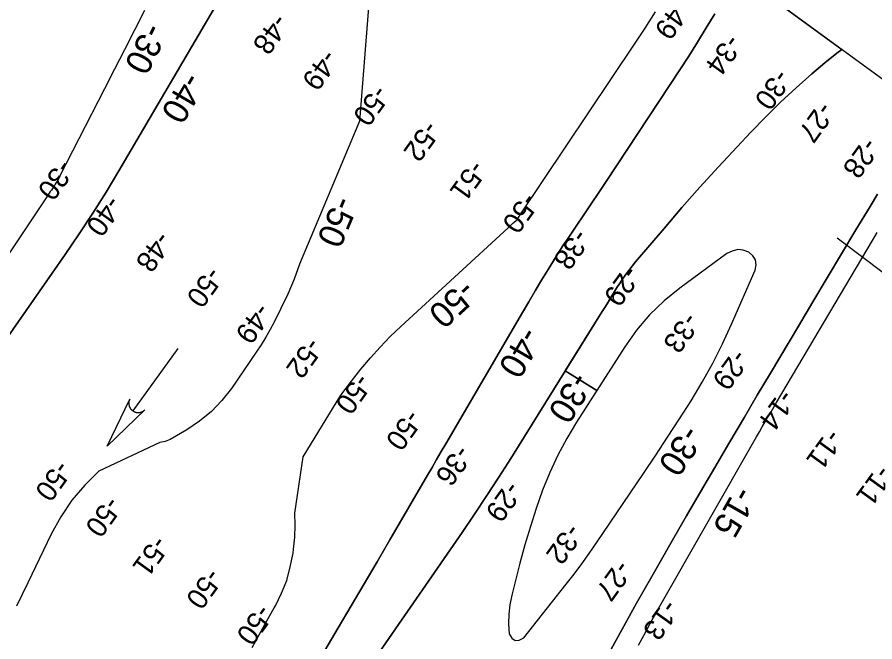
# Model space of a CAD drawing. Extents: x 3879599 to 3900814, y 146526 to 168888.
# Drawn here: x 3895080 to 3896475, y 160981 to 161997 of the extents above; entities that cross this region are included whole.
import ezdxf

# ---------------------------------------------------------------- set-up
doc = ezdxf.new("R2010")
doc.units = 0
for name, color, linetype in [('V-GRID-FRAM', 7, 'Continuous'), ('V-LEVE-TOET', 7, 'Continuous'), ('V-RIVR-RANG', 7, 'Continuous'), ('V-STRM-FLOW', 7, 'Continuous'), ('V-TOPO-DPTH', 7, 'Continuous'), ('V-TOPO-MAJR', 7, 'Continuous'), ('V-TOPO-MAJR-IDEN', 7, 'Continuous'), ('V-TOPO-MINR', 7, 'Continuous'), ('V-TOPO-MINR-IDEN', 7, 'Continuous')]:
    doc.layers.add(name, color=color, linetype=linetype)

msp = doc.modelspace()

# ---------------------------------------------------------------- linework, layer by layer
at = {"layer": 'V-GRID-FRAM'}
msp.add_lwpolyline([(3898776.6, 160226.4), (3889730.7, 148455.2), (3882888.9, 153284.4), (3891901.5, 165241.3), (3898776.6, 160226.4)], dxfattribs=at)
at = {"layer": 'V-LEVE-TOET'}
msp.add_lwpolyline([(3897419.3, 160907.4), (3897311, 160985.3), (3897169.2, 161092), (3896967.9, 161235.4), (3896798.9, 161357), (3896744.2, 161395.8), (3896682.3, 161439.8), (3896491.3, 161579.2), (3896414.2, 161636.9)], dxfattribs=at)
at = {"layer": 'V-STRM-FLOW'}
msp.add_line((3895341.7, 161457.7), (3895268.2, 161356.4), dxfattribs=at)
msp.add_lwpolyline([(3895287.7, 161357.7), (3895226.6, 161299), (3895263.4, 161375.3), (3895262.8, 161373.9), (3895262.4, 161372.5), (3895262.2, 161371.9), (3895262.1, 161371.4), (3895262, 161370.8), (3895262, 161370.2), (3895261.9, 161369.6), (3895261.9, 161368.9), (3895261.9, 161368.1), (3895261.9, 161367.7), (3895262, 161367.1), (3895262.1, 161366.4), (3895262.2, 161365.9), (3895262.3, 161365.2), (3895262.4, 161364.9), (3895262.5, 161364.4), (3895262.7, 161363.9), (3895262.8, 161363.4), (3895263, 161363), (3895263.2, 161362.6), (3895263.4, 161362), (3895263.7, 161361.5), (3895263.9, 161361.1), (3895264.2, 161360.6), (3895264.5, 161360.2), (3895264.7, 161359.9), (3895264.9, 161359.6), (3895265.2, 161359.2), (3895265.5, 161358.8), (3895265.9, 161358.4), (3895266.2, 161358.1), (3895266.5, 161357.8), (3895266.9, 161357.4), (3895267.2, 161357.1), (3895267.7, 161356.8), (3895268.2, 161356.4), (3895268.4, 161356.2), (3895268.6, 161356.1), (3895268.9, 161355.9), (3895269.2, 161355.7), (3895269.5, 161355.5), (3895269.8, 161355.3), (3895270.2, 161355.2), (3895270.4, 161355), (3895270.8, 161354.9), (3895271.1, 161354.7), (3895271.4, 161354.6), (3895272, 161354.4), (3895272.3, 161354.2), (3895272.6, 161354.2), (3895273, 161354), (3895273.3, 161354), (3895273.7, 161353.9), (3895274.1, 161353.8), (3895274.5, 161353.7), (3895274.8, 161353.6), (3895275.1, 161353.6), (3895275.5, 161353.6), (3895275.8, 161353.5), (3895276.2, 161353.5), (3895276.6, 161353.5), (3895277.1, 161353.5), (3895277.6, 161353.5), (3895277.9, 161353.5), (3895278.3, 161353.5), (3895278.7, 161353.6), (3895279.1, 161353.6), (3895279.4, 161353.6), (3895279.9, 161353.7), (3895280, 161353.7), (3895280.3, 161353.8), (3895280.5, 161353.8), (3895280.8, 161353.9), (3895281.2, 161354), (3895281.6, 161354.1), (3895281.9, 161354.2), (3895282.2, 161354.3), (3895282.6, 161354.5), (3895282.8, 161354.6), (3895283.2, 161354.7), (3895283.6, 161354.9), (3895283.9, 161355), (3895284.1, 161355.1), (3895284.3, 161355.2), (3895284.5, 161355.3), (3895284.8, 161355.5), (3895285, 161355.7), (3895285.3, 161355.8), (3895285.6, 161356), (3895285.9, 161356.3), (3895286.1, 161356.4), (3895286.4, 161356.6), (3895286.8, 161356.9), (3895287.1, 161357.1), (3895287.3, 161357.3), (3895287.4, 161357.5), (3895287.6, 161357.6)], close=True, dxfattribs=at)
at = {"layer": 'V-TOPO-DPTH'}
msp.add_line((3896253.5, 162066.8), (3896422, 161943.9), dxfattribs=at)
for points in [[(3894988.9, 161367.9), (3895158.5, 161610.6), (3895181.2, 161644), (3895203.5, 161677.8), (3895224.9, 161712.1), (3895245.8, 161746.7), (3895404.5, 162016.9), (3895405.5, 162018.7), (3895407.7, 162022.5), (3895409.9, 162026.1), (3895411.5, 162028.7), (3895412.3, 162030.1), (3895587.5, 162333.5), (3895598.3, 162352.6), (3895608.9, 162371.9), (3895619.1, 162391.3), (3895629, 162410.9), (3895669.6, 162492.7)], [(3894988.9, 161367.9), (3895158.5, 161610.6), (3895181.2, 161644), (3895203.5, 161677.8), (3895224.9, 161712.1), (3895245.8, 161746.7), (3895404.5, 162016.9), (3895405.5, 162018.7), (3895407.7, 162022.5), (3895409.9, 162026.1), (3895411.5, 162028.7), (3895412.3, 162030.1), (3895587.5, 162333.5), (3895598.3, 162352.6), (3895608.9, 162371.9), (3895619.1, 162391.3), (3895629, 162410.9), (3895669.6, 162492.7)], [(3895287.3, 162007.6), (3895271.1, 161975.6), (3895254.9, 161943.6), (3895238.6, 161911.7), (3895222.2, 161879.7), (3895149.1, 161737.4), (3895147.8, 161734.9), (3895146.5, 161732.4), (3895145.2, 161730), (3895143.8, 161727.6), (3895142.2, 161724.8), (3895140.9, 161722.7), (3895140.3, 161721.7), (3895137.6, 161717.8), (3895135.9, 161715.3), (3895134.2, 161712.8), (3895132.6, 161710.3), (3895130.9, 161707.8), (3894959.4, 161450.9)], [(3895287.3, 162007.6), (3895271.1, 161975.6), (3895254.9, 161943.6), (3895238.6, 161911.7), (3895222.2, 161879.7), (3895149.1, 161737.4), (3895147.8, 161734.9), (3895146.5, 161732.4), (3895145.2, 161730), (3895143.8, 161727.6), (3895142.2, 161724.8), (3895140.9, 161722.7), (3895140.3, 161721.7), (3895137.6, 161717.8), (3895135.9, 161715.3), (3895134.2, 161712.8), (3895132.6, 161710.3), (3895130.9, 161707.8), (3894959.4, 161450.9)], [(3895569.8, 160948.3), (3895602.5, 161003.3), (3895623.7, 161039), (3895644.8, 161074.8), (3895665.8, 161110.6), (3895686.7, 161146.6), (3895747.6, 161251.5), (3895755.1, 161264.3), (3895762.5, 161277.1), (3895769.9, 161289.9), (3895777.4, 161302.7), (3895902.2, 161516.3), (3895912.5, 161533.8), (3895922.9, 161551.3), (3895933.4, 161568.7), (3895944, 161586), (3895956.9, 161607), (3895961.1, 161613.8), (3895965.4, 161620.5), (3895969.8, 161627.2), (3895974.2, 161633.9), (3895989.8, 161656.8), (3896002, 161674.9), (3896014.1, 161693), (3896026.3, 161711.2), (3896038.3, 161729.4), (3896158, 161910.6), (3896172.7, 161933.2), (3896187.2, 161956), (3896201.3, 161979), (3896215.2, 162002.1)], [(3896215.2, 162002.1), (3896201.3, 161979), (3896187.2, 161956), (3896172.7, 161933.2), (3896158, 161910.6), (3896038.3, 161729.4), (3896026.3, 161711.2), (3896014.1, 161693), (3896002, 161674.9), (3895989.8, 161656.8), (3895974.2, 161633.9), (3895969.8, 161627.2), (3895965.4, 161620.5), (3895961.1, 161613.8), (3895956.9, 161607), (3895944, 161586), (3895933.4, 161568.7), (3895922.9, 161551.3), (3895912.5, 161533.8), (3895902.2, 161516.3), (3895777.4, 161302.7), (3895769.9, 161289.9), (3895762.5, 161277.1), (3895755.1, 161264.3), (3895747.6, 161251.5), (3895686.7, 161146.6), (3895665.8, 161110.6), (3895644.8, 161074.8), (3895623.7, 161039), (3895602.5, 161003.3), (3895569.8, 160948.3)], [(3896422, 161943.9), (3896413.7, 161937.8), (3896394.1, 161922.1), (3896373.2, 161904.3), (3896347.4, 161881.5), (3896322.1, 161858.2), (3896297.6, 161834.1), (3896273.6, 161809.4), (3896251.3, 161785.8), (3896220.9, 161753.2), (3896191, 161720.2), (3896161.5, 161686.8), (3896132.5, 161653), (3896086.2, 161598.5), (3896080.7, 161591.7), (3896075.3, 161584.7), (3896070.1, 161577.6), (3896065.1, 161570.4), (3896058.8, 161561.1), (3896057, 161558.4), (3896055.3, 161555.8), (3896053.6, 161553.1), (3896052, 161550.4), (3896047.6, 161543.1), (3896043.8, 161536.7), (3896039.9, 161530.4), (3896036, 161524.1), (3896032.1, 161517.7), (3895883.2, 161279), (3895863.9, 161248.6), (3895844.4, 161218.4), (3895824.4, 161188.4), (3895804.1, 161158.6), (3895660.6, 160950.9)], [(3896023, 161389.3), (3895971.8, 161421.1), (3896032.1, 161517.7), (3896036, 161524.1), (3896039.9, 161530.4), (3896043.8, 161536.7), (3896047.6, 161543.1), (3896052, 161550.4), (3896053.6, 161553.1), (3896055.3, 161555.8), (3896057, 161558.4), (3896058.8, 161561.1), (3896065.1, 161570.4), (3896070.1, 161577.6), (3896075.3, 161584.7), (3896080.7, 161591.7), (3896086.2, 161598.5), (3896132.5, 161653), (3896161.5, 161686.8), (3896191, 161720.2), (3896220.9, 161753.2), (3896251.3, 161785.8), (3896273.6, 161809.4), (3896297.6, 161834.1), (3896322.1, 161858.2), (3896347.4, 161881.5), (3896373.2, 161904.3), (3896394.1, 161922.1), (3896413.7, 161937.8), (3896422, 161943.9)], [(3896479.8, 161708.8), (3896467.6, 161688.7), (3896444.8, 161650.8), (3896421.3, 161611.7), (3896397.9, 161572.5), (3896374.5, 161533.4), (3896351.2, 161494.2), (3896305.6, 161417.4), (3896294.9, 161399.6), (3896284.3, 161381.7), (3896273.8, 161363.8), (3896263.2, 161345.9), (3896238, 161303.3), (3896215, 161264.1), (3896192, 161224.8), (3896169.2, 161185.4), (3896146.5, 161145.9), (3896112.5, 161086.6), (3896100.2, 161065), (3896088, 161043.4), (3896075.9, 161021.8), (3896063.9, 161000.1), (3895995.7, 160875.9)], [(3896479.8, 161708.8), (3896467.6, 161688.7), (3896444.8, 161650.8), (3896421.3, 161611.7), (3896397.9, 161572.5), (3896374.5, 161533.4), (3896351.2, 161494.2), (3896305.6, 161417.4), (3896294.9, 161399.6), (3896284.3, 161381.7), (3896273.8, 161363.8), (3896263.2, 161345.9), (3896238, 161303.3), (3896215, 161264.1), (3896192, 161224.8), (3896169.2, 161185.4), (3896146.5, 161145.9), (3896112.5, 161086.6), (3896100.2, 161065), (3896088, 161043.4), (3896075.9, 161021.8), (3896063.9, 161000.1), (3895995.7, 160875.9)], [(3895890.5, 160982.5), (3895897, 160983.2), (3895904.5, 160987.1), (3895973.6, 161074.2), (3895986.3, 161090.7), (3895998.8, 161107.4), (3896011, 161124.3), (3896022.9, 161141.4), (3896099.4, 161254.6), (3896119, 161283.9), (3896138.4, 161313.4), (3896157.6, 161343), (3896176.5, 161372.8), (3896194.6, 161403), (3896211.8, 161433.8), (3896227.5, 161465.2), (3896242.4, 161497.2), (3896280.7, 161584.9), (3896282.2, 161593.7), (3896281.4, 161601.6), (3896277.1, 161608.4), (3896270.6, 161614.4), (3896261.4, 161617.4), (3896252.4, 161618.4), (3896243.6, 161616.2), (3896234.9, 161612), (3896158, 161555.8), (3896132.5, 161534.9), (3896108.8, 161512.3), (3896087.7, 161487.2), (3896068.5, 161460.4), (3895990.1, 161337.8), (3895974.2, 161311.2), (3895959.6, 161283.9), (3895946.7, 161255.8), (3895935, 161227.1), (3895924.7, 161197.7), (3895915.1, 161168.2), (3895906.3, 161138.4), (3895898.1, 161108.4), (3895884.9, 161056.6), (3895881.9, 161041), (3895880, 161025.4), (3895879.8, 161009.6), (3895880.8, 160993.8), (3895885.2, 160986.6), (3895890.5, 160982.5)], [(3895890.5, 160982.5), (3895897, 160983.2), (3895904.5, 160987.1), (3895973.6, 161074.2), (3895986.3, 161090.7), (3895998.8, 161107.4), (3896011, 161124.3), (3896022.9, 161141.4), (3896099.4, 161254.6), (3896119, 161283.9), (3896138.4, 161313.4), (3896157.6, 161343), (3896176.5, 161372.8), (3896194.6, 161403), (3896211.8, 161433.8), (3896227.5, 161465.2), (3896242.4, 161497.2), (3896280.7, 161584.9), (3896282.2, 161593.7), (3896281.4, 161601.6), (3896277.1, 161608.4), (3896270.6, 161614.4), (3896261.4, 161617.4), (3896252.4, 161618.4), (3896243.6, 161616.2), (3896234.9, 161612), (3896158, 161555.8), (3896132.5, 161534.9), (3896108.8, 161512.3), (3896087.7, 161487.2), (3896068.5, 161460.4), (3896023, 161389.3)], [(3895660.6, 160950.9), (3895804.1, 161158.6), (3895824.4, 161188.4), (3895844.4, 161218.4), (3895863.9, 161248.6), (3895883.2, 161279), (3895970.6, 161419.1), (3895971.8, 161421.1), (3896023, 161389.3), (3896021.1, 161386.3)], [(3896021.1, 161386.3), (3895990.1, 161337.8), (3895974.2, 161311.2), (3895959.6, 161283.9), (3895946.7, 161255.8), (3895935, 161227.1), (3895924.7, 161197.7), (3895915.1, 161168.2), (3895906.3, 161138.4), (3895898.1, 161108.4), (3895884.9, 161056.6), (3895881.9, 161041), (3895880, 161025.4), (3895879.8, 161009.6), (3895880.8, 160993.8), (3895885.2, 160986.6), (3895890.5, 160982.5)]]:
    msp.add_lwpolyline(points, dxfattribs=at)
at = {"layer": 'V-TOPO-MAJR'}
for points in [[(3895651.9, 162012.1), (3895637, 161827.2), (3895539.5, 161594.9), (3895530.7, 161570.3), (3895520.5, 161546.2), (3895509.4, 161522.5), (3895498.7, 161501.4), (3895491.9, 161488.7), (3895484.8, 161476.1), (3895477.2, 161463.8), (3895469.2, 161451.8), (3895428.7, 161392.6), (3895413.2, 161373.1), (3895396.3, 161355.1), (3895377.1, 161339.6), (3895356.4, 161325.6), (3895329.2, 161309.8), (3895320.9, 161306.4), (3895312.4, 161304.5), (3895213.2, 161258), (3895190.1, 161235.2), (3895169, 161210.9), (3895151.2, 161184.1), (3895135.5, 161155.7), (3895097.8, 161076.3), (3895079.4, 161038.8)], [(3895462.6, 160971.2), (3895474.6, 160992.9), (3895486.6, 161014.5), (3895498.6, 161036.1), (3895500.4, 161039.2), (3895510.3, 161059.6), (3895518.7, 161080.6), (3895524.6, 161102.4), (3895529, 161124.7), (3895529.9, 161131.3), (3895531.7, 161150.7), (3895532.6, 161170.2), (3895531.8, 161189.6), (3895545.4, 161281.4), (3895600.9, 161372.1), (3895605.4, 161379.3), (3895610.2, 161386.3), (3895615.2, 161393.2), (3895620.4, 161399.9), (3895639.5, 161423.9), (3895654.8, 161442.2), (3895670.7, 161460), (3895687.3, 161477), (3895704.5, 161493.5), (3895879, 161654.1), (3895881.4, 161656.3), (3895883.8, 161658.5), (3895886.2, 161660.7), (3895888.6, 161662.9), (3895891.9, 161666), (3895892.6, 161666.7), (3895893.9, 161668.2), (3895895.6, 161670.8), (3895898.3, 161674.9), (3896084.7, 161952.6), (3896102, 161978.8), (3896118.9, 162005.2)]]:
    msp.add_lwpolyline(points, dxfattribs=at)
at = {"layer": 'V-TOPO-MINR'}
for points in [[(3895669.6, 162492.7), (3895629, 162410.9), (3895619.1, 162391.3), (3895608.9, 162371.9), (3895598.3, 162352.6), (3895587.5, 162333.5), (3895412.3, 162030.1), (3895411.5, 162028.7), (3895409.9, 162026.1), (3895407.7, 162022.5), (3895405.5, 162018.7), (3895404.5, 162016.9), (3895245.8, 161746.7), (3895224.9, 161712.1), (3895203.5, 161677.8), (3895181.2, 161644), (3895158.5, 161610.6), (3894988.9, 161367.9)], [(3895287.3, 162007.6), (3895271.1, 161975.6), (3895254.9, 161943.6), (3895238.6, 161911.7), (3895222.2, 161879.7), (3895149.1, 161737.4), (3895147.8, 161734.9), (3895146.5, 161732.4), (3895145.2, 161730), (3895143.8, 161727.6), (3895142.2, 161724.8), (3895140.9, 161722.7), (3895140.3, 161721.7), (3895137.6, 161717.8), (3895135.9, 161715.3), (3895134.2, 161712.8), (3895132.6, 161710.3), (3895130.9, 161707.8), (3894959.4, 161450.9)], [(3895569.8, 160948.3), (3895602.5, 161003.3), (3895623.7, 161039), (3895644.8, 161074.8), (3895665.8, 161110.6), (3895686.7, 161146.6), (3895747.6, 161251.5), (3895755.1, 161264.3), (3895762.5, 161277.1), (3895769.9, 161289.9), (3895777.4, 161302.7), (3895902.2, 161516.3), (3895912.5, 161533.8), (3895922.9, 161551.3), (3895933.4, 161568.7), (3895944, 161586), (3895956.9, 161607), (3895961.1, 161613.8), (3895965.4, 161620.5), (3895969.8, 161627.2), (3895974.2, 161633.9), (3895989.8, 161656.8), (3896002, 161674.9), (3896014.1, 161693), (3896026.3, 161711.2), (3896038.3, 161729.4), (3896158, 161910.6), (3896172.7, 161933.2), (3896187.2, 161956), (3896201.3, 161979), (3896215.2, 162002.1)], [(3895660.6, 160950.9), (3895804.1, 161158.6), (3895824.4, 161188.4), (3895844.4, 161218.4), (3895863.9, 161248.6), (3895883.2, 161279), (3896032.1, 161517.7), (3896036, 161524.1), (3896039.9, 161530.4), (3896043.8, 161536.7), (3896047.6, 161543.1), (3896052, 161550.4), (3896053.6, 161553.1), (3896055.3, 161555.8), (3896057, 161558.4), (3896058.8, 161561.1), (3896065.1, 161570.4), (3896070.1, 161577.6), (3896075.3, 161584.7), (3896080.7, 161591.7), (3896086.2, 161598.5), (3896132.5, 161653), (3896161.5, 161686.8), (3896191, 161720.2), (3896220.9, 161753.2), (3896251.3, 161785.8), (3896273.6, 161809.4), (3896297.6, 161834.1), (3896322.1, 161858.2), (3896347.4, 161881.5), (3896373.2, 161904.3), (3896394.1, 161922.1), (3896413.7, 161937.8), (3896422, 161943.9)], [(3895995.7, 160875.9), (3896063.9, 161000.1), (3896075.9, 161021.8), (3896088, 161043.4), (3896100.2, 161065), (3896112.5, 161086.6), (3896146.5, 161145.9), (3896169.2, 161185.4), (3896192, 161224.8), (3896215, 161264.1), (3896238, 161303.3), (3896263.2, 161345.9), (3896273.8, 161363.8), (3896284.3, 161381.7), (3896294.9, 161399.6), (3896305.6, 161417.4), (3896351.2, 161494.2), (3896374.5, 161533.4), (3896397.9, 161572.5), (3896421.3, 161611.7), (3896444.8, 161650.8), (3896467.6, 161688.7), (3896479.8, 161708.8)], [(3896090.9, 160975.3), (3896099.6, 160991.1), (3896110.1, 161010.5), (3896113.4, 161016.6), (3896116.8, 161022.8), (3896120.2, 161028.9), (3896123.7, 161034.9), (3896283, 161314.2), (3896287.6, 161322.2), (3896292.3, 161330.3), (3896296.9, 161338.3), (3896301.6, 161346.3), (3896306.6, 161354.9), (3896308.8, 161358.7), (3896311, 161362.4), (3896313.2, 161366.1), (3896315.4, 161369.9), (3896471.4, 161633.4), (3896479, 161646.3)], [(3895890.5, 160982.5), (3895897, 160983.2), (3895904.5, 160987.1), (3895973.6, 161074.2), (3895986.3, 161090.7), (3895998.8, 161107.4), (3896011, 161124.3), (3896022.9, 161141.4), (3896099.4, 161254.6), (3896119, 161283.9), (3896138.4, 161313.4), (3896157.6, 161343), (3896176.5, 161372.8), (3896194.6, 161403), (3896211.8, 161433.8), (3896227.5, 161465.2), (3896242.4, 161497.2), (3896280.7, 161584.9), (3896282.2, 161593.7), (3896281.4, 161601.6), (3896277.1, 161608.4), (3896270.6, 161614.4), (3896261.4, 161617.4), (3896252.4, 161618.4), (3896243.6, 161616.2), (3896234.9, 161612), (3896158, 161555.8), (3896132.5, 161534.9), (3896108.8, 161512.3), (3896087.7, 161487.2), (3896068.5, 161460.4), (3895990.1, 161337.8), (3895974.2, 161311.2), (3895959.6, 161283.9), (3895946.7, 161255.8), (3895935, 161227.1), (3895924.7, 161197.7), (3895915.1, 161168.2), (3895906.3, 161138.4), (3895898.1, 161108.4), (3895884.9, 161056.6), (3895881.9, 161041), (3895880, 161025.4), (3895879.8, 161009.6), (3895880.8, 160993.8), (3895885.2, 160986.6), (3895890.5, 160982.5)]]:
    msp.add_lwpolyline(points, dxfattribs=at)

# ---------------------------------------------------------------- texts
at = {"layer": 'V-RIVR-RANG'}
for s, rotation, p in [('-49', 234.1817, (3896153.2, 162028.7)), ('-48', 234.0899, (3895499.7, 162004.4)), ('-34', 234.1817, (3896236.4, 161971)), ('-49', 234.0899, (3895579.8, 161946.2)), ('-30', 234.1817, (3896315.9, 161914.4)), ('-50', 234.0899, (3895662.8, 161888.4)), ('-27', 234.1817, (3896386.5, 161861.4)), ('-52', 234.0899, (3895745, 161830.4)), ('-28', 234.0383, (3896459.5, 161803)), ('-30', 234.3507, (3895149.6, 161767.5)), ('-51', 234.0899, (3895820.3, 161766)), ('-50', 234.0899, (3895905.6, 161713.7)), ('-40', 234.3507, (3895228.4, 161708.7)), ('-48', 234.3507, (3895309.2, 161650.6)), ('-38', 234.0899, (3895988.9, 161654.5)), ('-50', 234.3507, (3895391.7, 161592.9)), ('-29', 234.0899, (3896070.6, 161594.9)), ('-49', 234.3507, (3895471.3, 161534)), ('-33', 233.9483, (3896167.5, 161518.9)), ('-52', 234.3507, (3895553.9, 161477.8)), ('-29', 233.9483, (3896247.4, 161458.7)), ('-50', 234.3507, (3895633.7, 161419.5)), ('-14', 233.9483, (3896323.4, 161393.2)), ('-50', 234.3507, (3895715.8, 161360.6)), ('-11', 233.9483, (3896400.3, 161329)), ('-36', 234.3507, (3895796.8, 161303)), ('-50', 234.121, (3895145.6, 161277.9)), ('-11', 233.9483, (3896481.3, 161270.3)), ('-29', 234.3507, (3895878.1, 161244.2)), ('-50', 234.121, (3895227.2, 161219.6)), ('-32', 234.2083, (3895976.8, 161175.3)), ('-51', 234.121, (3895304.2, 161155.6)), ('-27', 234.2083, (3896057.1, 161115.8)), ('-50', 234.121, (3895391, 161102.6)), ('-50', 234.121, (3895473.1, 161044)), ('-13', 234.2083, (3896134.3, 161051.9))]:
    msp.add_text(s, height=33.5, rotation=rotation, dxfattribs=at).set_placement(p)
at = {"layer": 'V-TOPO-MAJR-IDEN'}
for rotation, p in [(247.2237, (3895598.3, 161708.2)), (222.6123, (3895805.4, 161572.3))]:
    msp.add_text('-50', height=41.5, rotation=rotation, dxfattribs=at).set_placement(p)
at = {"layer": 'V-TOPO-MINR-IDEN'}
for s, rotation, p in [('-30', 243.1162, (3895290, 161989.9)), ('-40', 239.5749, (3895353.6, 161909.8)), ('-40', 239.7116, (3895902.2, 161495.8)), ('-30', 238.0473, (3895984.8, 161422.2)), ('-30', 236.5858, (3896165.7, 161335.9)), ('-15', 240.2889, (3896250.5, 161236.3))]:
    msp.add_text(s, height=41.5, rotation=rotation, dxfattribs=at).set_placement(p)

doc.saveas('drawing.dxf')
